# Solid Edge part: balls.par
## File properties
Title: Bearing
Author: Abhinav Rai
Template: Normal.par
Last saved by: CADCIM
Revision: 10
Application: Solid Edge
Accuracy: 0.99
Material: aluminum
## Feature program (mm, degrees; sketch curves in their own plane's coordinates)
sketch for "unnamed RevolvedProtrusion 1" plane through (0, 0, 0) normal (0, -1, 0) x-axis (1, 0, 0)
  arc centre (0, 0) radius 6.604 from (0, 6.604) to (0, -6.604) cw
  line (0, 6.604) -> (0, -6.604)
revolve "unnamed RevolvedProtrusion 1" add full turn 360 deg
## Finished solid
Body 1: solid body, 1 face, 0 edges, 0 vertices.
  Faces by surface: sphere 1
Spherical faces by radius (mm): R6.604 x1
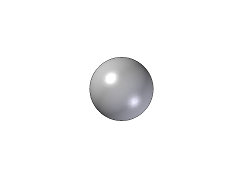
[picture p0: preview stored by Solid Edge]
